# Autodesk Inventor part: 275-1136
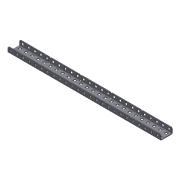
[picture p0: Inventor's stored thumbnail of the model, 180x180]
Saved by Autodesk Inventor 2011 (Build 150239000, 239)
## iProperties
Company: Autodesk Inc.
Created: 2005-08
Part Number: 275-1136
Document SubType Name: Sheet Metal
Designer: Autodesk Inc.
Density: 1 g/cm^3
Sheet Metal Rule: Default
Sheet Metal Width: 0.000 in
Sheet Metal Length: 0.000 in
Sheet Metal Area: 0.000 in^2
Catalog Web Link: http://www.vexrobotics.com/products/accessories/structure/c-channel.html
Description: VEX C-channel has holes on 0.500" increments. This structural member is perfect for building bigger robots. Excellent strength
Vendor: Innovation First, Inc.
Author: Autodesk Inc.
Title: VEX Robotics Kit of Parts
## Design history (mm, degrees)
node "Face1"
  sketch "Sketch1"
    geometry: L1 (-38.442, 14.458)-(275.248, 14.458); L2 (277.153, 12.553)-(277.153, 3.028); L3 (277.153, 3.028)-(-40.347, 3.028); L4 (-40.347, 3.028)-(-40.347, 12.553); L5 (-40.347, 12.553)-(-38.442, 14.458); L6 (275.248, 14.458)-(277.153, 12.553); 2 further points
    constraints: 16 end point, 4 point on line, 2 parallel, 1 horizontal, 1 perpendicular
    dimensions: "d5" = 11.43 distance of L3.end point (-40.347, 14.458); "d64" = 317.5 distance of L2.end L3.end; "d98" = 1.905 distance of L4.end point (-40.347, 14.458); "d99" = 1.905 distance of L1.start point (-40.347, 14.458) (= d98); "d102" = 1.905 distance of L1.end point (277.153, 14.458); "d103" = 1.905 distance of L2.start point (277.153, 14.458) (= d102)
node "Flange3"
sketch "Sketch10" dims "d134" = 25.4
  geometry: L1 (0, 0)-(0, 10.566) reference; L2 (0, 13.589)-(0, 9.779); L3 (0, 9.779)-(1.905, 11.684); L4 (1.905, 11.684)-(0, 13.589); L5 (317.5, 10.566)-(0, 10.566) reference; L6 (0, 13.589)-(-1.905, 11.684); L7 (-1.905, 11.684)-(0, 9.779); L8 (63.5, 13.589)-(61.595, 11.684); L9 (61.595, 11.684)-(63.5, 9.779); L10 (65.405, 11.684)-(63.5, 13.589); L11 (63.5, 9.779)-(65.405, 11.684); L12 (127, 13.589)-(125.095, 11.684); L13 (125.095, 11.684)-(127, 9.779); L14 (128.905, 11.684)-(127, 13.589); L15 (127, 9.779)-(128.905, 11.684); L16 (190.5, 13.589)-(188.595, 11.684); L17 (188.595, 11.684)-(190.5, 9.779); L18 (192.405, 11.684)-(190.5, 13.589); L19 (190.5, 9.779)-(192.405, 11.684); L20 (254, 13.589)-(252.095, 11.684); L21 (252.095, 11.684)-(254, 9.779); L22 (255.905, 11.684)-(254, 13.589); L23 (254, 9.779)-(255.905, 11.684); 1 further point
  constraints: 42 end point, 2 parallel, 1 collinear, 1 horizontal, 1 perpendicular, 1 point on line, 32 other
  dimensions: "d124" = 3.81 distance of L2.start L2.end; "d127" = 1.905 distance from line of L2 L3.end; "d131" = 63.5 distance of L2.start L8.start; "d160" = 1.1176 distance from line of L6.end L5
cut "Cut5" sketch "Sketch10" dims "d125" = 1.27 (= Thickness), "d126" = 0
sketch "Sketch11" dims "d143" = 25.4
  geometry: L1 (0, 0)-(313.69, 0) reference; L2 (-1.905, -9.296)-(-1.905, -1.905) reference; L3 (59.69, 0)-(61.595, -1.905); L4 (61.595, -1.905)-(63.5, 0); L5 (63.5, 0)-(61.595, 1.905); L6 (61.595, 1.905)-(59.69, 0); L7 (125.095, -1.905)-(127, 0); L8 (127, 0)-(125.095, 1.905); L9 (125.095, 1.905)-(123.19, 0); L10 (123.19, 0)-(125.095, -1.905); L11 (188.595, -1.905)-(190.5, 0); L12 (190.5, 0)-(188.595, 1.905); L13 (188.595, 1.905)-(186.69, 0); L14 (186.69, 0)-(188.595, -1.905); L15 (252.095, -1.905)-(254, 0); L16 (254, 0)-(252.095, 1.905); L17 (252.095, 1.905)-(250.19, 0); L18 (250.19, 0)-(252.095, -1.905); 1 further point
  constraints: 32 end point, 2 parallel, 2 perpendicular, 2 point on line, 1 horizontal, 24 other
  dimensions: "d136" = 1.905 horizontal distance of L5.end L3.start; "d137" = 63.5 distance from line of L5.end L2; "d140" = 63.5 distance of L4.end L7.end
cut "Cut6" sketch "Sketch11" dims "d145" = 1.27 (= Thickness), "d146" = 0
sketch "Sketch12"
  geometry: L1 (1.905, 9.296)-(61.595, 9.296) reference; L2 (0, 0)-(0, 7.391) reference; L3 (4.064, 6.502)-(8.636, 6.502); L4 (8.636, 6.502)-(8.636, 1.93); L5 (8.636, 1.93)-(4.064, 1.93); L6 (4.064, 1.93)-(4.064, 6.502); L7 (16.764, 6.502)-(21.336, 6.502); L8 (21.336, 6.502)-(21.336, 1.93); L9 (21.336, 1.93)-(16.764, 1.93); L10 (16.764, 1.93)-(16.764, 6.502); L11 (29.464, 6.502)-(34.036, 6.502); L12 (34.036, 6.502)-(34.036, 1.93); L13 (34.036, 1.93)-(29.464, 1.93); L14 (29.464, 1.93)-(29.464, 6.502); L15 (42.164, 6.502)-(46.736, 6.502); L16 (46.736, 6.502)-(46.736, 1.93); L17 (46.736, 1.93)-(42.164, 1.93); L18 (42.164, 1.93)-(42.164, 6.502); L19 (54.864, 6.502)-(59.436, 6.502); L20 (59.436, 6.502)-(59.436, 1.93); L21 (59.436, 1.93)-(54.864, 1.93); L22 (54.864, 1.93)-(54.864, 6.502); L23 (67.564, 6.502)-(72.136, 6.502); L24 (72.136, 6.502)-(72.136, 1.93); L25 (72.136, 1.93)-(67.564, 1.93); L26 (67.564, 1.93)-(67.564, 6.502); L27 (80.264, 6.502)-(84.836, 6.502); L28 (84.836, 6.502)-(84.836, 1.93); L29 (84.836, 1.93)-(80.264, 1.93); L30 (80.264, 1.93)-(80.264, 6.502); L31 (92.964, 6.502)-(97.536, 6.502); L32 (97.536, 6.502)-(97.536, 1.93); L33 (97.536, 1.93)-(92.964, 1.93); L34 (92.964, 1.93)-(92.964, 6.502); L35 (105.664, 6.502)-(110.236, 6.502); L36 (110.236, 6.502)-(110.236, 1.93); L37 (110.236, 1.93)-(105.664, 1.93); L38 (105.664, 1.93)-(105.664, 6.502); L39 (118.364, 6.502)-(122.936, 6.502); L40 (122.936, 6.502)-(122.936, 1.93); L41 (122.936, 1.93)-(118.364, 1.93); L42 (118.364, 1.93)-(118.364, 6.502); L43 (131.064, 6.502)-(135.636, 6.502); L44 (135.636, 6.502)-(135.636, 1.93); L45 (135.636, 1.93)-(131.064, 1.93); L46 (131.064, 1.93)-(131.064, 6.502); L47 (143.764, 6.502)-(148.336, 6.502); L48 (148.336, 6.502)-(148.336, 1.93); L49 (148.336, 1.93)-(143.764, 1.93); L50 (143.764, 1.93)-(143.764, 6.502); L51 (156.464, 6.502)-(161.036, 6.502); L52 (161.036, 6.502)-(161.036, 1.93); L53 (161.036, 1.93)-(156.464, 1.93); L54 (156.464, 1.93)-(156.464, 6.502); L55 (169.164, 6.502)-(173.736, 6.502); L56 (173.736, 6.502)-(173.736, 1.93); L57 (173.736, 1.93)-(169.164, 1.93); L58 (169.164, 1.93)-(169.164, 6.502); L59 (181.864, 6.502)-(186.436, 6.502); L60 (186.436, 6.502)-(186.436, 1.93); L61 (186.436, 1.93)-(181.864, 1.93); L62 (181.864, 1.93)-(181.864, 6.502); L63 (194.564, 6.502)-(199.136, 6.502); L64 (199.136, 6.502)-(199.136, 1.93)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
  constraints: 200 end point, 2 horizontal, 2 parallel, 1 perpendicular, 192 other
  dimensions: "d147" = 2.794 distance between parallel lines of L1 L3; "d148" = 4.572 distance of L5.end L3.start; "d149" = 4.572 distance of L3.start L3.end; "d150" = 4.064 distance between parallel lines of L2 L6; "d153" = 12.7 distance of L3.start L7.start
cut "Cut7" sketch "Sketch12" dims "d158" = 1.27 (= Thickness), "d159" = 0
sketch "Sketch13"
  geometry: L1 (62.713, 10.566)-(0, 10.566) reference; L2 (0, 0)-(0, 10.566) reference; L3 (4.064, 8.636)-(8.636, 8.636); L4 (8.636, 8.636)-(8.636, 4.064); L5 (8.636, 4.064)-(4.064, 4.064); L6 (4.064, 4.064)-(4.064, 8.636); L7 (0, 11.43)-(62.712, 11.43) reference; L8 (16.764, 8.636)-(21.336, 8.636); L9 (21.336, 4.064)-(16.764, 4.064); L10 (16.764, 4.064)-(16.764, 8.636); L11 (21.336, 8.636)-(21.336, 4.064); L12 (29.464, 8.636)-(34.036, 8.636); L13 (34.036, 4.064)-(29.464, 4.064); L14 (29.464, 4.064)-(29.464, 8.636); L15 (34.036, 8.636)-(34.036, 4.064); L16 (42.164, 8.636)-(46.736, 8.636); L17 (46.736, 4.064)-(42.164, 4.064); L18 (42.164, 4.064)-(42.164, 8.636); L19 (46.736, 8.636)-(46.736, 4.064); L20 (54.864, 8.636)-(59.436, 8.636); L21 (59.436, 4.064)-(54.864, 4.064); L22 (54.864, 4.064)-(54.864, 8.636); L23 (59.436, 8.636)-(59.436, 4.064); L24 (67.564, 8.636)-(72.136, 8.636); L25 (72.136, 4.064)-(67.564, 4.064); L26 (67.564, 4.064)-(67.564, 8.636); L27 (72.136, 8.636)-(72.136, 4.064); L28 (80.264, 8.636)-(84.836, 8.636); L29 (84.836, 4.064)-(80.264, 4.064); L30 (80.264, 4.064)-(80.264, 8.636); L31 (84.836, 8.636)-(84.836, 4.064); L32 (92.964, 8.636)-(97.536, 8.636); L33 (97.536, 4.064)-(92.964, 4.064); L34 (92.964, 4.064)-(92.964, 8.636); L35 (97.536, 8.636)-(97.536, 4.064); L36 (105.664, 8.636)-(110.236, 8.636); L37 (110.236, 4.064)-(105.664, 4.064); L38 (105.664, 4.064)-(105.664, 8.636); L39 (110.236, 8.636)-(110.236, 4.064); L40 (118.364, 8.636)-(122.936, 8.636); L41 (122.936, 4.064)-(118.364, 4.064); L42 (118.364, 4.064)-(118.364, 8.636); L43 (122.936, 8.636)-(122.936, 4.064); L44 (131.064, 8.636)-(135.636, 8.636); L45 (135.636, 4.064)-(131.064, 4.064); L46 (131.064, 4.064)-(131.064, 8.636); L47 (135.636, 8.636)-(135.636, 4.064); L48 (143.764, 8.636)-(148.336, 8.636); L49 (148.336, 4.064)-(143.764, 4.064); L50 (143.764, 4.064)-(143.764, 8.636); L51 (148.336, 8.636)-(148.336, 4.064); L52 (156.464, 8.636)-(161.036, 8.636); L53 (161.036, 4.064)-(156.464, 4.064); L54 (156.464, 4.064)-(156.464, 8.636); L55 (161.036, 8.636)-(161.036, 4.064); L56 (169.164, 8.636)-(173.736, 8.636); L57 (173.736, 4.064)-(169.164, 4.064); L58 (169.164, 4.064)-(169.164, 8.636); L59 (173.736, 8.636)-(173.736, 4.064); L60 (181.864, 8.636)-(186.436, 8.636); L61 (186.436, 4.064)-(181.864, 4.064); L62 (181.864, 4.064)-(181.864, 8.636); L63 (186.436, 8.636)-(186.436, 4.064); L64 (194.564, 8.636)-(199.136, 8.636)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; 1 further point
  constraints: 200 end point, 2 horizontal, 2 parallel, 1 perpendicular, 192 other
  dimensions: "d161" = 4.064 distance between parallel lines of L2 L6; "d162" = 4.572 distance of L5.end L3.start; "d163" = 4.572 distance of L4.end L5.end; "d164" = 2.794 distance between parallel lines of L7 L3; "d177" = 12.7 distance of L3.start L8.start
cut "Cut8" sketch "Sketch13" dims "d173" = 1.27 (= Thickness), "d174" = 0
mirror "Mirror1"
body "Solid1"
face "Plate1" dims "Thickness" = 1.27
sketch "Sketch8"
  geometry: L1 (0, 12.7)-(-317.5, 12.7); L2 (-317.5, 12.7)-(-317.5, 0); 2 other entities
  constraints: 4 end point, 4 other
face "Plate4" dims "d107" = 1.27 (= BendReliefWidth), "d108" = 0.635 (= BendReliefDepth), "d109" = 2.54 (= MinimumRemnant), "d110" = 0.8636 (= BendRadius), "d111" = 12.7, "d112" = 90 deg, "d113" = 0.8636 (= BendRadius), "d114" = 5.08 (= CornerReliefSize), "d115" = 1.27 (= GapSize), "d116" = 1.27 (= JacobiRadiusSize), "SeamGap" = 0.00508, "Thickness" = 1.27
bend "Bend3" dims "d107" = 1.27 (= BendReliefWidth), "d108" = 0.635 (= BendReliefDepth), "d109" = 2.54 (= MinimumRemnant), "d110" = 0.8636 (= BendRadius), "d111" = 12.7, "d112" = 90 deg, "d113" = 0.8636 (= BendRadius), "SeamGap" = 0.00508, "Thickness" = 1.27
feature "Corner2" dims "d111" = 12.7, "d112" = 90 deg, "d114" = 5.08 (= CornerReliefSize), "d115" = 1.27 (= GapSize), "d116" = 1.27 (= JacobiRadiusSize)
other parameters: "BendRadius" = 0.8636, "BendReliefWidth" = 1.27 (= Thickness), "BendReliefDepth" = 0.635 (= 0.5 x Thickness), "CornerReliefSize" = 5.08 (= 4 x Thickness), "MinimumRemnant" = 2.54 (= 2 x Thickness), "TransitionRadius" = 0.8636 (= BendRadius), "d14" = 0.8636 (= BendRadius), "JacobiRadiusSize" = 1.27 (= Thickness), "GapSize" = 1.27 (= Thickness), "d156" = 25.4, "d180" = 25.4
